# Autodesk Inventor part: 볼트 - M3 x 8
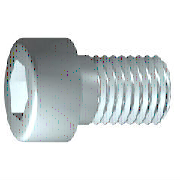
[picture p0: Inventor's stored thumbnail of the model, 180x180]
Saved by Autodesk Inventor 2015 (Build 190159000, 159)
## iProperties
IsCustomPart: 0
Created: 2012-02
Part Number: 볼트 - M3 x 8
Material: 스테인리스강
Description: 6각 소켓 머리 캡 나사
Document SubType Name: Modeling
Standard: ISO 4762
Designer: mduedu
Standard Revision: Fourth edition 2004-03-01
Standards Organization: ISO
Language: ko-KR
Size Designation: M3 x 8
Categories: <MemberInstance><Categories><Category DisplayName="조임쇠" InternalName="e4da775c-781d-43d5-af7c-5136215cf5a6" Mnemonic="FSTN"><Category DisplayName="볼트" InternalN
Density: 7.75 g/cm^3
Appearance: 반광택
Author: mduedu
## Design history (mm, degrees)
sketch "스케치1"
  geometry: L1 (-0.867, 0)-(8, 0); L2 (8, 0)-(8, 1.5); L3 (8, 1.5)-(1.25, 1.5); L4 (1.25, 1.5)-(0.943, 1.5); L5 (0.943, 1.5)-(0, 1.5); L6 (0, 1.5)-(0, 2.75); L7 (0, 2.75)-(-3, 2.75); L8 (-3, 2.75)-(-3, 1.443); L9 (-3, 1.443)-(-1.7, 1.443); L10 (-1.7, 1.443)-(-0.867, 0); L11 (-5.2, 0)-(10.2, 0) reference; L12 (0, -0.55)-(0, 3.3) reference; L13 (1.25, 1.5)-(0, 1.5)
  constraints: 22 end point, 6 parallel, 2 collinear, 2 perpendicular, 1 horizontal, 1 point on line
  dimensions: "d1" = 6.75 distance from line of L3.end L2 (= GEL); "d2" = 0.30683 distance of L4.end L3.end (computed from GAL); "d3" = 3 distance between parallel lines of L8 L6 (= KOH); "d4" = 1.3 distance of L8.end L9.end (= INTI); "d5" = 60 deg angle of L10 L1; "d6" = 3 diameter of L3 L1 (= GD); "d7" = 3 diameter of L5 L1 (= BDM); "d8" = 2.88675 diameter of L9 L1 (= 1.1547 x SW); "d9" = 5.5 diameter of L7 L1 (= KOD); "d26" = 8 distance between parallel lines of L12 L2 (= NLG)
revolve "본체" sketch "스케치1" stored, may be unused: angle "d10" = 90 deg
sketch "스케치2"
  geometry: L1 (0, -3.85)-(0, 3.85) reference; L2 (-3.85, 0)-(3.85, 0) reference; L3 (1.443, 0)-(0.722, -1.25); L4 (0.722, -1.25)-(-0.722, -1.25); L5 (-0.722, -1.25)-(-1.443, 0); L6 (-1.443, 0)-(-0.722, 1.25); L7 (-0.722, 1.25)-(0.722, 1.25); L8 (0.722, 1.25)-(1.443, 0); 2 further points
  constraints: 12 end point, 1 coincident, 1 horizontal alignment, 1 point on line, 12 other
extrude "슬롯" join sketch "스케치2" stored distance "d11" = 10; taper "d12" = 0 deg
workplane "Work Plane1"
fillet "Fillet2" dims "d30" = 0.1 (= R)
body "Solid1"
fillet "모깎기1" dims "d17" = 0.3 (= RR)
feature "스레드" dims "d13" = 6.75 (= GEL), "d14" = 0
chamfer "모따기1" distance "d15" = 0.30673 (= -0.5 x SPD + 0.5 x GD); stored, may be unused: second distance "d16" = 0.30673 (= GUL), angle "d27" = 45 deg
other parameters: "GD" = 3 [user parameter; used in 2 equation terms], "NLG" = 8 [user parameter; used in 1 equation term], "GEL" = 6.75 [user parameter; used in 2 equation terms], "KOD" = 5.5 [user parameter; used in 1 equation term], "KOH" = 3 [user parameter; used in 1 equation term], "INTI" = 1.3 [user parameter; used in 1 equation term], "GAL" = 0.30673 (= 0.61345 x PTC) [user parameter; used in 1 equation term], "GUL" = 0.30673 (= 0.61345 x PTC) [user parameter; used in 1 equation term], "BDM" = 3 (= NND) [user parameter; used in 1 equation term], "SW" = 2.5 [user parameter; used in 2 equation terms], "RR" = 0.3 [user parameter; used in 1 equation term], "SPD" = 2.38655 (= NND - 1.2269 x PTC) [user parameter; used in 1 equation term], "d19" = 0, "d28" = 0, "d29" = 0, "R" = 0.1 [user parameter; used in 1 equation term], "TOA" = 30 deg [user parameter], "GD1" = 2.38655 (= THREADDIA - 1.2269 x PTC) [user parameter], "THREADDIA" = 3 [user parameter; used in 1 equation term], "FAWI" = 45 deg [user parameter], "PTC" = 0.5 [user parameter; used in 5 equation terms], "NND" = 3 [user parameter; used in 2 equation terms], "E0" = 2.8875 (= 1.155 x SW) [user parameter]
